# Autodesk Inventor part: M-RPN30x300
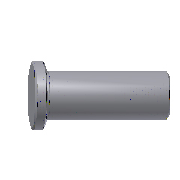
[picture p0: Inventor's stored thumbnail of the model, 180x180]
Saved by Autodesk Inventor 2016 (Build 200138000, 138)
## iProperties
Created: 2015-02
Part Number: M-RPN30x300
Material: SUJ 2
Description: Return Pin
Document SubType Name: Modeling
Designer: Sandeep
Standard Revision: 1
Manufacturer: FUTABA
Language: en-US
Size Designation: 30x300
Categories: <MemberInstance><Categories><Category DisplayName="Mold" InternalName="349578f2-f4d4-4954-8c09-8e99297a61c0" Mnemonic="MOLD"><Category DisplayName="Return Compo
Mass: 6.63789 g
Surface Area: 25.7048 cm^2
Volume: 6.63789 cm^3
Density: 7.85 g/cm^3
Appearance: Aluminum - Dark
IsCustomPart: 1
Author: Sandeep
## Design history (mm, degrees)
body "Solid1"
revolve "Revolution1" stored, may be unused: angle "d41" = 90 deg
revolve "Revolution2" stored, may be unused: angle "d48" = 90 deg
chamfer "Chamfer1" distance "d49" = 0.5; stored, may be unused: second distance "d50" = 2, angle "d51" = 45 deg
sketch "Sketch1"
  geometry: L1 (0, -15)-(0, 62) reference; L2 (0, -4)-(17.5, -4); L3 (17.5, -4)-(17.5, 0); L4 (17.5, 0)-(15, 0); L5 (15, 0)-(15, 296); L6 (15, 296)-(0, 296); L7 (0, 296)-(0, -4); 1 further point
  constraints: 12 end point, 3 perpendicular, 2 parallel, 2 point on line, 1 collinear, 1 horizontal alignment
  dimensions: "d28" = 4 distance between parallel lines of L2 L4 (= H_); "d29" = 35 diameter of L3 L1 (= D); "d31" = 30 diameter of L5 L1 (= d_); "d33" = 300 distance between parallel lines of L2 L6 (= L)
sketch "Sketch2" dims "d28" = 4 (= H_), "d29" = 35 (= D), "d31" = 30 (= d_), "d33" = 300 (= L)
  geometry: L1 (15, 296)-(15, 0) reference; L2 (-15, 0)-(15, 0) reference; L3 (15, 0)-(14.8, 0); L4 (14.5, 0.3)-(14.5, 0.9); L5 (14.8, 1.2)-(15, 1.2); L6 (15, 1.2)-(15, 0); L7 (0, -10.275)-(0, 61.212) reference; A1 r 0.3 centre (14.8, 0.9) between (14.8, 1.2) and (14.5, 0.9); A2 r 0.3 centre (14.8, 0.3) between (14.5, 0.3) and (14.8, 0); 1 further point
  constraints: 8 end point, 4 point on circle, 4 tangent, 2 centre point, 2 parallel, 1 equal radius, 1 horizontal, 1 perpendicular
  dimensions: "d45" = 0.3 radius of A1; "d46" = 1.2 distance between parallel lines of L2 L5; "d47" = 0.5 distance between parallel lines of L4 L1
other parameters: "d_" = 30 [user parameter; used in 1 equation term], "L" = 300 [user parameter; used in 1 equation term], "D" = 35 [user parameter; used in 1 equation term], "H_" = 4 [user parameter; used in 1 equation term], "d44" = 0, "d52" = 0, "d53" = 0
